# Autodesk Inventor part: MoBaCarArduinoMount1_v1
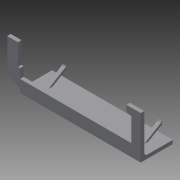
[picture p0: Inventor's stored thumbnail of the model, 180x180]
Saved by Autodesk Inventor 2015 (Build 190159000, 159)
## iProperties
Created: 2017-05
Part Number: MoBaCarArduinoMount1_v1
Material: Generisch
Document SubType Name: Modeling
Designer: Andreas
Density: 1 g/cm^3
Appearance: Vorgabe
Author: Andreas
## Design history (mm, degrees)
sketch "Skizze1"
  geometry: L1 (0, 0)-(169, 0); L2 (169, 0)-(169, 45); L3 (169, 45)-(0, 45); L4 (0, 45)-(0, 0)
  constraints: 8 end point, 2 parallel, 1 horizontal, 1 perpendicular
  dimensions: "d0" = 169 distance of L3.end L2.end; "d1" = 45 distance of L2.end L1.end
extrude "Extrusion1" new body sketch "Skizze1" distance "d2" = 5; taper "d3" = 0 deg
sketch "Skizze2"
  geometry: L1 (-169, 0)-(0, 0) reference; L2 (0, 0)-(0, 5) reference; L3 (-169, 5)-(0, 5) reference; L4 (-169, 0)-(-169, 5) reference; L5 (-169, 5)-(-169, 60); L6 (-169, 60)-(-149, 60); L7 (-149, 60)-(-149, 53); L8 (-152, 50)-(-156, 50); L9 (-156, 50)-(-156, 17); L10 (0, 5)-(-169, 5) reference; L11 (-156, 17)-(0, 17); L12 (-152, 50)-(-149, 53); L13 (18, 60)-(18, 17); L14 (18, 17)-(0, 5); L15 (0, 17)-(0, 30); L16 (18, 60)-(3, 60); L17 (3, 60)-(3, 30); L18 (3, 30)-(0, 30); 2 further points
  constraints: 26 end point, 6 perpendicular, 2 horizontal, 2 point on line, 2 vertical
  dimensions: "d4" = 55 distance of L3.start L5.end; "d5" = 20 distance of L5.end L6.end; "d6" = 10 distance of L6.end point (-149, 50); "d7" = 7 distance of point (-149, 50) L8.end; "d8" = 12 distance between parallel lines of L11 L3; "d9" = 3 distance of L8.start point (-149, 50); "d10" = 3 distance of L7.end point (-149, 50) (= d9); "d12" = 43 distance of L13.start L13.end; "d14" = 156 distance of L9.end L11.end; "d76" = 15 distance of L13.start L16.end; "d77" = 30 distance of L16.end L17.end; "d78" = 3 distance of L17.end L15.end
extrude "Extrusion2" join sketch "Skizze2" distance "d15" = 5; taper "d16" = 0 deg
chamfer "Fase1" distance "d17" = 3; stored, may be unused: second distance "d18" = 2, angle "d19" = 45 deg
workplane "Arbeitsebene1"
sketch "Skizze3"
  geometry: L1 (169, 8)-(0, 8) reference; L2 (169, 8)-(169, 45) reference; L3 (169, 45)-(0, 45) reference; L4 (0, 45)-(0, 8) reference; L5 (20, 20)-(15, 20); L6 (15, 20)-(15, 25); L7 (15, 25)-(20, 25); L8 (20, 25)-(20, 20); L9 (149, 20)-(154, 20); L10 (154, 20)-(154, 25); L11 (154, 25)-(149, 25); L12 (149, 25)-(149, 20); 4 further points
  constraints: 16 end point, 4 parallel, 2 horizontal, 2 perpendicular, 1 midpoint
  dimensions: "d21" = 5 distance of L6.end L7.end; "d22" = 5 distance of L5.end L6.end; "d23" = 5 distance of L11.end L10.end; "d24" = 5 distance of L10.end L9.end; "d25" = 12 distance between parallel lines of L1 L5; "d26" = 15 distance between parallel lines of L4 L6; "d27" = 12 distance between parallel lines of L1 L9; "d28" = 15 distance between parallel lines of L2 L10
  node "Projizierte Kontur2"
sketch "Skizze4"
  geometry: L1 (0, 0)-(169, 0) reference; L2 (169, 0)-(169, 5) reference; L3 (0, 5)-(169, 5) reference; L4 (0, 0)-(0, 5) reference; L5 (149, 20)-(154, 20); L6 (154, 20)-(154, 15); L7 (154, 15)-(149, 15); L8 (149, 15)-(149, 20); L9 (20, 20)-(15, 20); L10 (15, 20)-(15, 15); L11 (15, 15)-(20, 15); L12 (20, 15)-(20, 20); 3 further points
  constraints: 16 end point, 4 parallel, 2 horizontal, 2 perpendicular
  dimensions: "d29" = 5 distance of L6.end L7.end; "d30" = 5 distance of L5.end L6.end; "d31" = 5 distance of L11.end L10.end; "d32" = 5 distance of L10.end L9.end; "d33" = 10 distance between parallel lines of L3 L7; "d34" = 10 distance between parallel lines of L3 L11; "d62" = 15 distance between parallel lines of L4 L10
  node "Projizierte Kontur3"
workplane "Arbeitsebene2"
  workaxis "Arbeitsachse1"
  workaxis "Arbeitsachse2"
workplane "Arbeitsebene3"
extrude "Extrusion4" join sketch "Skizze4" distance "d60" = 1; taper "d61" = 0 deg
sketch "Skizze7"
  geometry: L1 (0, 45)-(0, 0) reference; L2 (0, 0)-(5, 0) reference; L3 (5, 8)-(5, 0) reference; L4 (5, 45)-(5, 8) reference; L5 (0, 45)-(5, 45) reference; L6 (20, 45)-(5, 20); 7 further points
  constraints: 2 end point
feature "Rippe2" sketch "Skizze7" dims "d54" = 3, "d55" = 5, "d56" = 0, "d57" = 0, "d58" = 1, "d59" = 1
sketch "Skizze8"
  geometry: L1 (0, 5)-(169, 5) reference; L2 (15, 5)-(20, 5) reference; L3 (20, 5)-(15, 5) reference; L4 (15, 15)-(20, 15); L5 (20, 15)-(20, 20); L6 (20, 20)-(15, 20); L7 (15, 20)-(15, 15); L8 (0, 0)-(0, 5) reference; 4 further points
  constraints: 8 end point, 2 parallel, 1 horizontal, 1 perpendicular
  dimensions: "d63" = 5 distance of L6.end L5.end; "d64" = 5 distance of L5.end L4.end; "d65" = 10 distance between parallel lines of L1 L4; "d66" = 15 distance between parallel lines of L8 L7
workplane "Arbeitsebene4"
sketch "Skizze9"
  geometry: L1 (-5, 20)-(-20, 45); 5 further points
  constraints: 2 end point
extrude "Extrusion5" join sketch "Skizze8" distance "d68" = 1; taper "d69" = 0 deg
feature "Rippe3" dims "d70" = 3, "d71" = 5, "d72" = 0, "d73" = 0, "d74" = 1, "d75" = 1
node "Volumenkörper1"
node "Projizierte Kontur1"
node "Projizierte Kontur4"
other parameters: "d20" = 90 deg, "d45" = -17.5, "d67" = -17.5
